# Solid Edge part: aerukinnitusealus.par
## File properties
Author: Argo
Template: Normal.par
Last saved by: Argo
Revision: 10
Application: Solid Edge
Material: Aluminum, 7075-T6
Face Style: Aluminum
Fill Style: ANSI38(Aluminum)
Virtual Style: Polished aluminum
Coef. of Thermal Exp: 2.3e-05
Thermal Conductivity: 121.0
Specific Heat: 920.0
Modulus of Elasticity: 71705472800.0
Poission's Ratio: 0.33
Yield Stress: 503317261.0
Ultimate Stress: 572264831.0
Elongation: 0.0
Density: 2795,000 kg/m^3
Accuracy: 0,990
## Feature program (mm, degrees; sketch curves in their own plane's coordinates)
sketch for "unnamed Protrusion 1" plane through (0, 0, 0) normal (0, 0, 1) x-axis (1, 0, 0)
  line (-13, -2.5) -> (13, -2.5)
  arc centre (13, -0.5) radius 2 from (13, -2.5) to (15, -0.5) ccw
  line (15, -0.5) -> (15, 0.5)
  arc centre (13, 0.5) radius 2 from (15, 0.5) to (13, 2.5) ccw
  line (13, 2.5) -> (-13, 2.5)
  arc centre (-13, 0.5) radius 2 from (-13, 2.5) to (-15, 0.5) ccw
  line (-15, 0.5) -> (-15, -0.5)
  arc centre (-13, -0.5) radius 2 from (-13, -2.5) to (-15, -0.5) cw
extrude "unnamed Protrusion 1" add finite 2 along +normal
sketch for "unnamed Cutout 1" #1 plane through (0, 0, 2) normal (0, 0, 1) x-axis (1, 0, 0)
  circle centre (-7.5, 0) radius 1
sketch for "unnamed Cutout 1" #2 plane through (0, 0, 2) normal (0, 0, 1) x-axis (1, 0, 0)
  circle centre (7.5, 0) radius 1
extrude "unnamed Cutout 1" cut to key point along -normal
sketch for "ExtrudedProtrusion_2" plane through (0, 0, 2) normal (0, 0, 1) x-axis (1, 0, 0)
  circle centre (0, 0) radius 2.5
extrude "ExtrudedProtrusion_2" add finite 10 along +normal
sketch for "ExtrudedProtrusion_3" plane through (0, 0, 12) normal (0, 0, 1) x-axis (1, 0, 0)
  circle centre (0, 0) radius 1.5
extrude "ExtrudedProtrusion_3" add finite 2 along +normal
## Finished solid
Body 1: solid body, 17 faces, 35 edges, 18 vertices.
  Faces by surface: plane 9, cylinder 8
  Edges by curve: line 18, circle 17
Bounding box of the edges (mm): 30.000 x 5.000 x 14.000, from (-15, -2.5, 0) to (15, 2.5, 14).
Cylindrical faces by radius (mm): R1 x2, R1.5 x1, R2 x4, R2.5 x1
Planar faces by outward normal: +x 1, +y 1, +z 4, -x 1, -y 1, -z 1
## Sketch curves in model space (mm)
circle centre (0, 0, 12) radius 1.5
circle centre (0, 0, 12) radius 1.5
circle centre (0, 0, 2) radius 2.5
circle centre (7.5, 0, 2) radius 1
circle centre (-7.5, 0, 2) radius 1
arc centre (13, -0.5, 0) radius 2 from (13, -2.5, 0) through (14.4547, -1.8725, 0) to (15, -0.5, 0)
line (15, -0.5, 0) -> (15, 0.5, 0)
arc centre (13, 0.5, 0) radius 2 from (15, 0.5, 0) through (14.3725, 1.9547, 0) to (13, 2.5, 0)
line (13, 2.5, 0) -> (-13, 2.5, 0)
arc centre (-13, 0.5, 0) radius 2 from (-13, 2.5, 0) through (-14.4547, 1.8725, 0) to (-15, 0.5, 0)
line (-15, 0.5, 0) -> (-15, -0.5, 0)
arc centre (-13, -0.5, 0) radius 2 from (-13, -2.5, 0) through (-14.4547, -1.8725, 0) to (-15, -0.5, 0)
line (-13, -2.5, 0) -> (13, -2.5, 0)
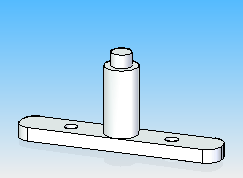
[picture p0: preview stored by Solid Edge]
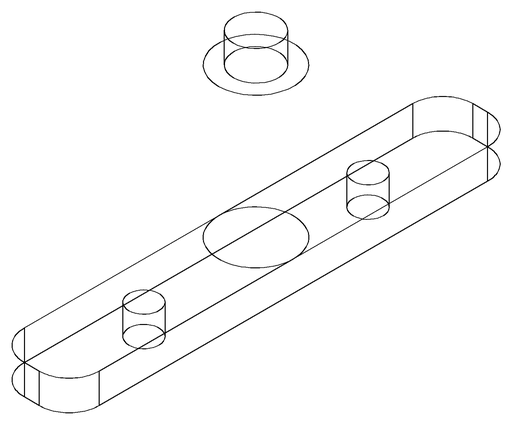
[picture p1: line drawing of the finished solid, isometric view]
